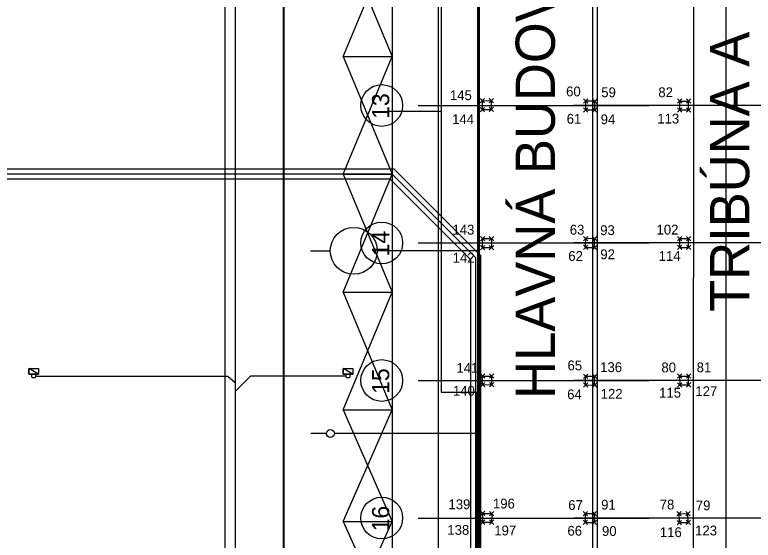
# Model space of a CAD drawing. Extents: x -264205 to -263659, y -1242401 to -1242060.
# Drawn here: x -263937.81 to -263900.22, y -1242183.01 to -1242156.26 of the extents above; entities that cross this region are included whole.
import ezdxf

# ---------------------------------------------------------------- set-up
doc = ezdxf.new("R2010")
doc.units = 0
for name, color, linetype in [('BOD_CISLO', 7, 'Continuous'), ('BOD_SYMBOL', 7, 'Continuous'), ('KFA_SO_10-1_BETONOVE_STLPY', 7, 'Continuous'), ('KFA_SO_10-1_STRECHY', 7, 'Continuous'), ('KFA_SO_10-1_TRIBUNA_A_HLAVNA_BUDOVA', 7, 'Continuous'), ('OBRUBNIKY_KOMUNIKACIE_PROJEKT', 7, 'Continuous'), ('OSI_STAVBY_KFA', 7, 'Continuous'), ('POPIS', 7, 'Continuous'), ('SITUACIA_DSP_2D', 7, 'Continuous'), ('TDZ_VODOROVNE_PROJEKT', 7, 'Continuous')]:
    doc.layers.add(name, color=color, linetype=linetype)

msp = doc.modelspace()

# ---------------------------------------------------------------- linework, layer by layer
at = {"layer": 'BOD_SYMBOL'}
for p, q in [((-263914.114, -1242160.752), (-263913.893, -1242160.532)), ((-263913.893, -1242160.752), (-263914.114, -1242160.532)), ((-263913.663, -1242160.747), (-263913.442, -1242160.525)), ((-263913.442, -1242160.747), (-263913.663, -1242160.525)), ((-263908.848, -1242160.766), (-263908.627, -1242160.546)), ((-263908.627, -1242160.766), (-263908.848, -1242160.546)), ((-263908.392, -1242160.774), (-263908.171, -1242160.552)), ((-263908.171, -1242160.774), (-263908.392, -1242160.552)), ((-263904.072, -1242160.765), (-263903.851, -1242160.545)), ((-263903.851, -1242160.765), (-263904.072, -1242160.545)), ((-263903.618, -1242160.769), (-263903.397, -1242160.549)), ((-263903.397, -1242160.769), (-263903.618, -1242160.549)), ((-263914.111, -1242161.198), (-263913.889, -1242160.978)), ((-263913.889, -1242161.198), (-263914.111, -1242160.978)), ((-263913.66, -1242161.194), (-263913.439, -1242160.972)), ((-263913.439, -1242161.194), (-263913.66, -1242160.972)), ((-263908.851, -1242161.218), (-263908.63, -1242160.997)), ((-263908.63, -1242161.218), (-263908.851, -1242160.997)), ((-263908.394, -1242161.218), (-263908.174, -1242160.998)), ((-263908.174, -1242161.218), (-263908.394, -1242160.998)), ((-263904.073, -1242161.215), (-263903.852, -1242160.994)), ((-263903.852, -1242161.215), (-263904.073, -1242160.994)), ((-263903.62, -1242161.221), (-263903.399, -1242160.999)), ((-263903.399, -1242161.221), (-263903.62, -1242160.999)), ((-263914.106, -1242167.779), (-263913.884, -1242167.559)), ((-263913.884, -1242167.779), (-263914.106, -1242167.559)), ((-263913.649, -1242167.779), (-263913.427, -1242167.559)), ((-263913.427, -1242167.779), (-263913.649, -1242167.559)), ((-263908.851, -1242167.772), (-263908.629, -1242167.551)), ((-263908.629, -1242167.772), (-263908.851, -1242167.551)), ((-263908.398, -1242167.775), (-263908.177, -1242167.555)), ((-263908.177, -1242167.775), (-263908.398, -1242167.555)), ((-263904.073, -1242167.769), (-263903.852, -1242167.548)), ((-263903.852, -1242167.769), (-263904.073, -1242167.548)), ((-263903.617, -1242167.771), (-263903.395, -1242167.549)), ((-263903.395, -1242167.771), (-263903.617, -1242167.549)), ((-263914.105, -1242168.227), (-263913.883, -1242168.005)), ((-263913.883, -1242168.227), (-263914.105, -1242168.005)), ((-263913.649, -1242168.224), (-263913.427, -1242168.002)), ((-263913.427, -1242168.224), (-263913.649, -1242168.002)), ((-263908.856, -1242168.221), (-263908.634, -1242168.001)), ((-263908.634, -1242168.221), (-263908.856, -1242168.001)), ((-263908.398, -1242168.225), (-263908.177, -1242168.004)), ((-263908.177, -1242168.225), (-263908.398, -1242168.004)), ((-263904.073, -1242168.218), (-263903.851, -1242167.997)), ((-263903.851, -1242168.218), (-263904.073, -1242167.997)), ((-263903.614, -1242168.218), (-263903.393, -1242167.998)), ((-263903.393, -1242168.218), (-263903.614, -1242167.998)), ((-263914.104, -1242174.765), (-263913.883, -1242174.543)), ((-263913.883, -1242174.765), (-263914.104, -1242174.543)), ((-263913.645, -1242174.765), (-263913.424, -1242174.545)), ((-263913.424, -1242174.765), (-263913.645, -1242174.545)), ((-263908.859, -1242174.772), (-263908.638, -1242174.552)), ((-263908.638, -1242174.772), (-263908.859, -1242174.552)), ((-263908.404, -1242174.775), (-263908.182, -1242174.553)), ((-263908.182, -1242174.775), (-263908.404, -1242174.553)), ((-263904.071, -1242174.765), (-263903.85, -1242174.545)), ((-263903.85, -1242174.765), (-263904.071, -1242174.545)), ((-263903.618, -1242174.765), (-263903.397, -1242174.545)), ((-263903.397, -1242174.765), (-263903.618, -1242174.545)), ((-263914.104, -1242175.208), (-263913.883, -1242174.988)), ((-263913.883, -1242175.208), (-263914.104, -1242174.988)), ((-263913.644, -1242175.204), (-263913.424, -1242174.982)), ((-263913.424, -1242175.204), (-263913.644, -1242174.982)), ((-263908.861, -1242175.221), (-263908.639, -1242174.999)), ((-263908.639, -1242175.221), (-263908.861, -1242174.999)), ((-263908.405, -1242175.221), (-263908.184, -1242175.001)), ((-263908.184, -1242175.221), (-263908.405, -1242175.001)), ((-263904.068, -1242175.215), (-263903.847, -1242174.994)), ((-263903.847, -1242175.215), (-263904.068, -1242174.994)), ((-263903.617, -1242175.213), (-263903.395, -1242174.992)), ((-263903.395, -1242175.213), (-263903.617, -1242174.992)), ((-263914.093, -1242181.759), (-263913.872, -1242181.539)), ((-263913.872, -1242181.759), (-263914.093, -1242181.539)), ((-263913.639, -1242181.765), (-263913.417, -1242181.545)), ((-263913.417, -1242181.765), (-263913.639, -1242181.545)), ((-263908.87, -1242181.765), (-263908.649, -1242181.543)), ((-263908.649, -1242181.765), (-263908.87, -1242181.543)), ((-263908.411, -1242181.766), (-263908.19, -1242181.546)), ((-263908.19, -1242181.766), (-263908.411, -1242181.546)), ((-263904.105, -1242181.776), (-263903.883, -1242181.556)), ((-263903.883, -1242181.776), (-263904.105, -1242181.556)), ((-263903.648, -1242181.769), (-263903.427, -1242181.549)), ((-263903.427, -1242181.769), (-263903.648, -1242181.549)), ((-263914.095, -1242182.204), (-263913.875, -1242181.982)), ((-263913.875, -1242182.204), (-263914.095, -1242181.982)), ((-263913.644, -1242182.204), (-263913.422, -1242181.982)), ((-263913.422, -1242182.204), (-263913.644, -1242181.982)), ((-263908.87, -1242182.215), (-263908.649, -1242181.994)), ((-263908.649, -1242182.215), (-263908.87, -1242181.994)), ((-263908.41, -1242182.213), (-263908.189, -1242181.992)), ((-263908.189, -1242182.213), (-263908.41, -1242181.992)), ((-263904.092, -1242182.225), (-263903.871, -1242182.004)), ((-263903.871, -1242182.225), (-263904.092, -1242182.004)), ((-263903.636, -1242182.215), (-263903.415, -1242181.994)), ((-263903.415, -1242182.215), (-263903.636, -1242181.994))]:
    msp.add_line(p, q, dxfattribs=at)
at = {"layer": 'KFA_SO_10-1_BETONOVE_STLPY'}
for p, q in [((-263914.003, -1242160.642), (-263913.552, -1242160.636)), ((-263914, -1242161.088), (-263914.003, -1242160.642)), ((-263913.552, -1242160.636), (-263913.55, -1242161.083)), ((-263908.741, -1242161.107), (-263908.737, -1242160.656)), ((-263908.281, -1242160.663), (-263908.737, -1242160.656)), ((-263908.284, -1242161.108), (-263908.281, -1242160.663)), ((-263903.961, -1242160.655), (-263903.963, -1242161.104)), ((-263903.961, -1242160.655), (-263903.508, -1242160.659)), ((-263903.509, -1242161.11), (-263903.508, -1242160.659)), ((-263914, -1242161.088), (-263913.55, -1242161.083)), ((-263908.741, -1242161.107), (-263908.284, -1242161.108)), ((-263903.963, -1242161.104), (-263903.509, -1242161.11)), ((-263913.994, -1242168.116), (-263913.995, -1242167.669)), ((-263913.538, -1242167.669), (-263913.995, -1242167.669)), ((-263913.538, -1242167.669), (-263913.538, -1242168.113)), ((-263908.745, -1242168.111), (-263908.74, -1242167.661)), ((-263908.287, -1242167.665), (-263908.74, -1242167.661)), ((-263908.287, -1242168.114), (-263908.287, -1242167.665)), ((-263903.963, -1242167.658), (-263903.506, -1242167.66)), ((-263903.963, -1242167.658), (-263903.962, -1242168.107)), ((-263903.503, -1242168.108), (-263903.506, -1242167.66)), ((-263913.994, -1242168.116), (-263913.538, -1242168.113)), ((-263908.745, -1242168.111), (-263908.287, -1242168.114)), ((-263903.962, -1242168.107), (-263903.503, -1242168.108)), ((-263913.993, -1242175.098), (-263913.993, -1242174.654)), ((-263913.993, -1242174.654), (-263913.535, -1242174.655)), ((-263913.535, -1242174.655), (-263913.534, -1242175.093)), ((-263908.75, -1242175.11), (-263908.748, -1242174.662)), ((-263908.748, -1242174.662), (-263908.293, -1242174.664)), ((-263908.295, -1242175.111), (-263908.293, -1242174.664)), ((-263903.96, -1242174.655), (-263903.508, -1242174.655)), ((-263903.96, -1242174.655), (-263903.958, -1242175.104)), ((-263903.506, -1242175.102), (-263903.508, -1242174.655)), ((-263913.993, -1242175.098), (-263913.534, -1242175.093)), ((-263908.75, -1242175.11), (-263908.295, -1242175.111)), ((-263903.958, -1242175.104), (-263903.506, -1242175.102)), ((-263913.985, -1242182.093), (-263913.982, -1242181.649)), ((-263913.982, -1242181.649), (-263913.528, -1242181.655)), ((-263913.528, -1242181.655), (-263913.533, -1242182.093)), ((-263908.759, -1242182.104), (-263908.759, -1242181.654)), ((-263908.759, -1242181.654), (-263908.301, -1242181.656)), ((-263908.3, -1242182.102), (-263908.301, -1242181.656)), ((-263903.994, -1242181.666), (-263903.537, -1242181.659)), ((-263903.994, -1242181.666), (-263903.981, -1242182.114)), ((-263903.525, -1242182.104), (-263903.537, -1242181.659)), ((-263913.985, -1242182.093), (-263913.533, -1242182.093)), ((-263908.759, -1242182.104), (-263908.3, -1242182.102)), ((-263903.981, -1242182.114), (-263903.525, -1242182.104))]:
    msp.add_line(p, q, dxfattribs=at)
at = {"layer": 'KFA_SO_10-1_STRECHY'}
msp.add_line((-263908.157, -1242227.179), (-263908.136, -1242101.59), dxfattribs=at)
at = {"layer": 'KFA_SO_10-1_TRIBUNA_A_HLAVNA_BUDOVA'}
for p, q in [((-263914.23, -1242196.348), (-263914.235, -1242132.417)), ((-263914.23, -1242196.348), (-263914.235, -1242132.417)), ((-263903.251, -1242196.344), (-263903.234, -1242132.417)), ((-263903.251, -1242196.344), (-263903.234, -1242132.417)), ((-263916.245, -1242132.722), (-263916.25, -1242195.816))]:
    msp.add_line(p, q, dxfattribs=at)
at = {"layer": 'OBRUBNIKY_KOMUNIKACIE_PROJEKT'}
msp.add_line((-263914.143, -1242196.333), (-263914.143, -1242132.433), dxfattribs=at)
at = {"layer": 'OSI_STAVBY_KFA'}
for p, q in [((-263908.393, -1242083.237), (-263908.393, -1242246.707)), ((-263901.618, -1242083.237), (-263901.618, -1242246.707)), ((-263917.265, -1242160.882), (-263905.505, -1242160.882)), ((-263917.265, -1242160.882), (-263905.505, -1242160.882)), ((-263792.653, -1242160.882), (-263909.343, -1242160.882)), ((-263917.265, -1242167.882), (-263905.505, -1242167.882)), ((-263917.265, -1242167.882), (-263905.505, -1242167.882)), ((-263792.653, -1242167.882), (-263909.343, -1242167.882)), ((-263917.265, -1242174.882), (-263905.505, -1242174.882)), ((-263917.265, -1242174.882), (-263905.505, -1242174.882)), ((-263792.653, -1242174.882), (-263909.343, -1242174.882)), ((-263917.265, -1242181.882), (-263905.505, -1242181.882)), ((-263917.265, -1242181.882), (-263905.505, -1242181.882)), ((-263792.653, -1242181.882), (-263909.343, -1242181.882))]:
    msp.add_line(p, q, dxfattribs=at)
for centre in [(-263919.125, -1242160.882), (-263919.125, -1242167.882), (-263919.125, -1242174.882), (-263919.125, -1242181.882)]:
    msp.add_circle(centre, 1.064, dxfattribs=at)
at = {"layer": 'SITUACIA_DSP_2D'}
for p, q in [((-263924.143, -1242082.64), (-263924.143, -1242185.14)), ((-263916.093, -1242118.282), (-263916.093, -1242175.482)), ((-263914.218, -1242196.332), (-263914.218, -1242132.432)), ((-263914.143, -1242196.333), (-263914.143, -1242132.433)), ((-263926.593, -1242155.252), (-263926.593, -1242204.252)), ((-263916.093, -1242161.182), (-263918.763, -1242161.182)), ((-263918.489, -1242164.132), (-263946.093, -1242164.132)), ((-263918.489, -1242164.132), (-263914.1, -1242168.521)), ((-263918.593, -1242164.382), (-263946.093, -1242164.382)), ((-263918.593, -1242164.382), (-263914.35, -1242168.625)), ((-263918.696, -1242164.632), (-263946.093, -1242164.632)), ((-263918.696, -1242164.632), (-263914.6, -1242168.728)), ((-263922.745, -1242168.282), (-263921.745, -1242168.282)), ((-263914.143, -1242168.282), (-263919.355, -1242168.282)), ((-263914.6, -1242168.728), (-263914.6, -1242199.693)), ((-263914.35, -1242168.625), (-263914.35, -1242199.59)), ((-263914.1, -1242168.521), (-263914.1, -1242199.486)), ((-263937.093, -1242174.553), (-263937.093, -1242174.263)), ((-263937.093, -1242174.263), (-263936.593, -1242174.263)), ((-263936.593, -1242174.553), (-263937.093, -1242174.263)), ((-263936.593, -1242174.553), (-263937.093, -1242174.263)), ((-263937.093, -1242174.263), (-263937.093, -1242174.553)), ((-263936.593, -1242174.263), (-263936.593, -1242174.553)), ((-263921.093, -1242174.553), (-263921.093, -1242174.263)), ((-263921.093, -1242174.263), (-263920.593, -1242174.263)), ((-263920.593, -1242174.553), (-263921.093, -1242174.263)), ((-263920.593, -1242174.553), (-263921.093, -1242174.263)), ((-263921.093, -1242174.263), (-263921.093, -1242174.553)), ((-263920.593, -1242174.263), (-263920.593, -1242174.553)), ((-263936.593, -1242174.553), (-263937.093, -1242174.553)), ((-263937.093, -1242174.553), (-263936.593, -1242174.553)), ((-263936.743, -1242174.653), (-263926.953, -1242174.653)), ((-263926.953, -1242174.653), (-263926.593, -1242174.978)), ((-263925.798, -1242174.653), (-263926.593, -1242175.448)), ((-263920.944, -1242174.653), (-263925.798, -1242174.653)), ((-263920.593, -1242174.553), (-263921.093, -1242174.553)), ((-263921.093, -1242174.553), (-263920.593, -1242174.553)), ((-263916.093, -1242175.482), (-263914.293, -1242175.482)), ((-263914.293, -1242175.482), (-263914.293, -1242210.482)), ((-263921.938, -1242177.582), (-263922.738, -1242177.582)), ((-263915.293, -1242177.582), (-263921.538, -1242177.582)), ((-263914.143, -1242177.582), (-263915.293, -1242177.582))]:
    msp.add_line(p, q, dxfattribs=at)
for centre, radius in [((-263920.55, -1242168.282), 1.195), ((-263936.843, -1242174.653), 0.1), ((-263920.844, -1242174.653), 0.1), ((-263921.738, -1242177.582), 0.2)]:
    msp.add_circle(centre, radius, dxfattribs=at)
at = {"layer": 'TDZ_VODOROVNE_PROJEKT'}
for p, q in [((-263924.088, -1242241.458), (-263924.093, -1242087.307)), ((-263927.093, -1242184.007), (-263927.093, -1242134.007)), ((-263918.593, -1242141.207), (-263918.593, -1242187.557)), ((-263921.093, -1242152.382), (-263918.593, -1242158.382)), ((-263921.093, -1242158.382), (-263918.593, -1242152.382)), ((-263921.093, -1242158.382), (-263918.593, -1242158.382)), ((-263921.093, -1242158.382), (-263918.593, -1242164.382)), ((-263921.093, -1242164.382), (-263918.593, -1242158.382)), ((-263921.093, -1242164.382), (-263918.593, -1242164.382)), ((-263921.093, -1242164.382), (-263918.593, -1242170.382)), ((-263921.093, -1242170.382), (-263918.593, -1242164.382)), ((-263921.093, -1242170.382), (-263918.593, -1242170.382)), ((-263921.093, -1242170.382), (-263918.593, -1242176.382)), ((-263921.093, -1242176.382), (-263918.593, -1242170.382)), ((-263921.093, -1242176.382), (-263918.593, -1242176.382)), ((-263921.093, -1242176.382), (-263918.593, -1242182.062)), ((-263921.093, -1242182.062), (-263918.593, -1242176.382)), ((-263921.093, -1242182.062), (-263918.593, -1242182.062)), ((-263921.093, -1242182.062), (-263918.593, -1242187.557)), ((-263921.093, -1242187.557), (-263918.593, -1242182.062))]:
    msp.add_line(p, q, dxfattribs=at)

# ---------------------------------------------------------------- texts
at = {"layer": 'BOD_CISLO'}
for s, p in [('60', (-263909.74, -1242160.419)), ('59', (-263907.952, -1242160.461)), ('82', (-263905.046, -1242160.458)), ('145', (-263915.656, -1242160.609)), ('144', (-263915.54, -1242161.827)), ('61', (-263909.711, -1242161.809)), ('94', (-263907.98, -1242161.835)), ('113', (-263905.1, -1242161.802)), ('143', (-263915.527, -1242167.453)), ('63', (-263909.553, -1242167.457)), ('93', (-263908.005, -1242167.478)), ('102', (-263905.138, -1242167.451)), ('62', (-263909.628, -1242168.795)), ('92', (-263908, -1242168.707)), ('114', (-263905.029, -1242168.793)), ('142', (-263915.516, -1242168.88)), ('141', (-263915.323, -1242174.49)), ('65', (-263909.669, -1242174.365)), ('136', (-263908.006, -1242174.453)), ('80', (-263904.89, -1242174.468)), ('81', (-263903.095, -1242174.463)), ('140', (-263915.501, -1242175.654)), ('64', (-263909.685, -1242175.835)), ('122', (-263907.98, -1242175.812)), ('115', (-263905.006, -1242175.754)), ('127', (-263903.163, -1242175.676)), ('139', (-263915.73, -1242181.433)), ('196', (-263913.467, -1242181.397)), ('67', (-263909.631, -1242181.472)), ('91', (-263907.956, -1242181.454)), ('78', (-263904.976, -1242181.445)), ('79', (-263903.138, -1242181.491)), ('138', (-263915.785, -1242182.738)), ('197', (-263913.397, -1242182.766)), ('66', (-263909.672, -1242182.782)), ('123', (-263903.173, -1242182.768)), ('90', (-263907.914, -1242182.796)), ('116', (-263904.968, -1242182.853))]:
    msp.add_text(s, height=0.5, dxfattribs=at).set_placement(p)
at = {"layer": 'OSI_STAVBY_KFA'}
for s, p in [('13', (-263918.744, -1242161.562)), ('14', (-263918.744, -1242168.562)), ('15', (-263918.744, -1242175.562)), ('16', (-263918.744, -1242182.562))]:
    msp.add_text(s, height=0.875, rotation=90, dxfattribs=at).set_placement(p)
at = {"layer": 'POPIS'}
for s, p in [('HLAVNÁ BUDOVA', (-263910.309, -1242175.819)), ('TRIBÚNA A', (-263900.416, -1242171.391))]:
    msp.add_text(s, height=2, rotation=90, dxfattribs=at).set_placement(p)

doc.saveas('drawing.dxf')
